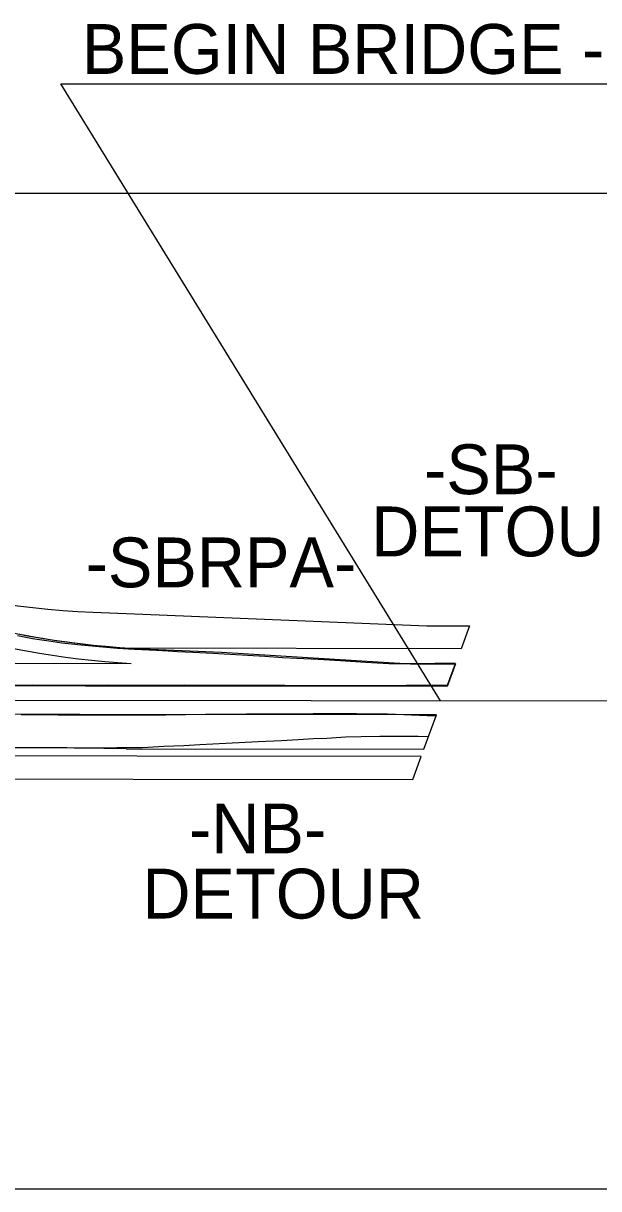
# Model space of a CAD drawing. Extents: x 2241278 to 2254132, y 649924 to 670434.
# Drawn here: x 2248712 to 2249319, y 662535 to 663765 of the extents above; entities that cross this region are included whole.
import ezdxf

# ---------------------------------------------------------------- set-up
doc = ezdxf.new("R2010")
doc.units = 0
for name, color, linetype in [('Pattern 4', 7, 'Continuous'), ('Prop DSN Text', 7, 'Continuous'), ('Prop Horizontal Alignment', 7, 'Continuous'), ('Prop RDY Alternate Text Yellow', 7, 'Continuous'), ('Prop Shade Heavy', 7, 'Continuous')]:
    doc.layers.add(name, color=color, linetype=linetype)

msp = doc.modelspace()

# ---------------------------------------------------------------- linework, layer by layer
at = {"layer": 'Pattern 4'}
for p, q in [((2249159.336078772, 663066.7082313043), (2249167.7898785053, 663089.5677081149)), ((2249139.3899553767, 663012.772964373), (2249147.4540124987, 663034.5785586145))]:
    msp.add_line(p, q, dxfattribs=at)
for points in [[(2249167.7898785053, 663089.5677081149), (2249159.228492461, 663089.6424579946), (2249146.0990382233, 663089.5987739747), (2249127.642966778, 663089.2384639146), (2249097.5813274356, 663089.3209915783), (2249072.995964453, 663090.7130612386), (2249046.585730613, 663092.4051507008), (2249022.749567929, 663093.7523472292), (2249000.2995952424, 663094.9941430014), (2248985.193567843, 663095.7356244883), (2248966.5289831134, 663097.176320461), (2248948.495280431, 663098.1608593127), (2248923.9210604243, 663099.4279203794), (2248911.7947710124, 663100.163497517), (2248890.6725089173, 663101.173491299), (2248874.5517428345, 663101.8486880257), (2248864.6596188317, 663102.5512727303), (2248852.3917822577, 663103.206333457), (2248844.7678805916, 663103.8149647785), (2248828.688629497, 663104.324355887), (2248811.1618813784, 663105.4249124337), (2248799.551019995, 663106.369470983), (2248772.9562313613, 663108.9442451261), (2248752.62412637, 663111.1444754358), (2248738.7589628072, 663113.3230295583), (2248721.7288937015, 663115.7938782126), (2248705.705206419, 663118.8617455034)], [(2248681.9061098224, 663066.8638399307), (2248721.980150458, 663067.1694241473), (2248761.240811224, 663066.7010286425), (2248800.863517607, 663067.1570449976), (2248842.0763467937, 663066.8143067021), (2248882.333280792, 663066.9523774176), (2248924.7630850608, 663066.7396779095), (2248956.3882947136, 663066.6797537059), (2248987.76190992, 663066.8051155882), (2249021.886788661, 663066.4531272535), (2249061.7030959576, 663066.3046694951), (2249115.5846840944, 663066.9045448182), (2249136.3788786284, 663067.1248550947), (2249159.336078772, 663066.7082313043)], [(2249147.4540124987, 663034.5785586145), (2249137.987843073, 663034.5810139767), (2249113.3537883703, 663035.4461736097), (2249096.0591444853, 663036.0409517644), (2249081.8694685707, 663036.2487396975), (2249063.4448014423, 663036.6168420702), (2249039.823357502, 663036.65930015), (2249017.749458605, 663036.7005023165), (2248993.8817138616, 663036.1691265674), (2248969.0655973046, 663036.3347705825), (2248946.839353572, 663036.0837042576), (2248929.014164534, 663035.7109308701), (2248904.093923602, 663035.6575296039), (2248862.1154721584, 663035.2516447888), (2248824.419881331, 663035.0624553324), (2248786.7746820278, 663035.0205108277), (2248748.5551320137, 663035.2078753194), (2248709.569692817, 663035.4523364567)], [(2248697.996508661, 663000.8356622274), (2248701.6137060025, 663000.8835208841), (2248747.9133080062, 663000.8673465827), (2248781.9784494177, 663000.6100270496), (2248810.475118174, 663001.1631734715), (2248837.7173311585, 663001.1015211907), (2248859.9624694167, 663002.3098727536), (2248881.2325595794, 663003.0213568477), (2248898.018917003, 663004.038114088), (2248925.4469335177, 663005.4166768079), (2248959.443907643, 663007.2343067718), (2248984.239088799, 663008.4419906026), (2249001.7018443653, 663009.432305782), (2249018.1251939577, 663010.3309372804), (2249031.9899260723, 663010.9687554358), (2249051.592922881, 663012.1635181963), (2249068.0811014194, 663012.7258490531), (2249088.0510972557, 663012.798439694), (2249104.8641020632, 663012.8310636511), (2249128.325150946, 663012.8929500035), (2249139.3899553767, 663012.772964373)]]:
    msp.add_lwpolyline(points, dxfattribs=at)
at = {"layer": 'Prop DSN Text'}
for p, q in [((2251198.4216737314, 663585.5258229), (2247330.488405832, 663585.4218419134)), ((2248845.7197187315, 663104.6785400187), (2248920.8129643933, 663101.5733055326)), ((2248920.8129643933, 663101.5733055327), (2249120.317026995, 663089.3464329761)), ((2248395.317459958, 663090.2059901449), (2248825.5682528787, 663089.6958861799)), ((2249167.6872778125, 663089.2902709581), (2249158.8155779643, 663065.3007723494)), ((2249134.4184033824, 662999.3296511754), (2249147.7259531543, 663035.3138990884)), ((2247330.516632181, 662535.4449286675), (2251198.4499030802, 662535.4373335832))]:
    msp.add_line(p, q, dxfattribs=at)
for points in [[(2249120.3170269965, 663089.346432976), (2249167.6872778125, 663089.2902709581)], [(2249158.8155779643, 663065.3007723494), (2248395.289052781, 663066.2060069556)], [(2249147.7259531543, 663035.3138990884), (2248395.2535438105, 663036.2060279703)], [(2248820.2105342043, 662999.7021750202), (2249134.4184033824, 662999.3296511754)]]:
    msp.add_lwpolyline(points, dxfattribs=at)
for centre, radius, start, end in [((2248884.8876708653, 664051.8690549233), 948.0000000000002, 240.0836274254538, 267.63207033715), ((2248884.887670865, 664051.8690549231), 963.9999999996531, 240.08637361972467, 266.4720945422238), ((2248689.937627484, 655542.7146767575), 7458.125339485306, 88.99914965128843, 90.91982228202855)]:
    msp.add_arc(centre, radius, start, end, dxfattribs=at)
at = {"layer": 'Prop Horizontal Alignment'}
msp.add_line((2247428.233538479, 663052.3525343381), (2250137.966660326, 663049.1398834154), dxfattribs=at)
at = {"layer": 'Prop RDY Alternate Text Yellow'}
for p, q in [((2249151.82076662, 663050.3090548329), (2248751.597791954, 663701.2802170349)), ((2248751.597791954, 663701.2802170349), (2249815.432743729, 663701.2802170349))]:
    msp.add_line(p, q, dxfattribs=at)
at = {"layer": 'Prop Shade Heavy'}
for p, q in [((2248785.1649569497, 663143.8556338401), (2248837.982516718, 663141.6715371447)), ((2248837.982516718, 663141.6715371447), (2249137.4865089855, 663129.3261050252)), ((2249173.6017443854, 663105.2832700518), (2249173.6017443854, 663105.2832700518)), ((2249122.589470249, 662967.3436530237), (2249131.461170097, 662991.3331516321))]:
    msp.add_line(p, q, dxfattribs=at)
for points in [[(2249137.4865089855, 663129.3261050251), (2249182.4734442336, 663129.2727686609), (2249173.6017443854, 663105.2832700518)], [(2249173.6017443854, 663105.2832700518), (2248826.072496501, 663105.6952995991)], [(2249131.461170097, 662991.3331516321), (2248532.0654020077, 662992.0437933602)], [(2248532.03699483, 662968.0438101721), (2249122.589470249, 662967.3436530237)]]:
    msp.add_lwpolyline(points, dxfattribs=at)
for centre, radius, start, end in [((2248824.332909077, 664091.0461487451), 947.9999999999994, 237.09835811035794, 267.63207033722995), ((2248884.8876708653, 664051.8690549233), 948.0000000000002, 240.0836274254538, 266.4430096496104)]:
    msp.add_arc(centre, radius, start, end, dxfattribs=at)

# ---------------------------------------------------------------- texts
at = {"layer": 'Prop RDY Alternate Text Yellow'}
for s, p in [('BEGIN BRIDGE -L- 23+31.55', (2248773.65830357, 663711.8156379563)), ('-SB-', (2249134.6616001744, 663268.2935110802)), ('DETOUR', (2249078.8755077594, 663202.7237278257)), ('-SBRPA-', (2248777.6891273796, 663170.031384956)), ('-NB-', (2248886.783590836, 662889.1448194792)), ('DETOUR', (2248837.496848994, 662820.5046912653))]:
    msp.add_text(s, height=52.59375, dxfattribs=at).set_placement(p)

doc.saveas('drawing.dxf')
